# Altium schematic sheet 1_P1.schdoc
size 307 x 218 mm; Symbol: Drawing-Symbol_A4; Device: Drawing-Symbol_A4; Company: 嘉立创EDA; Version: V1.0; Page Size: A4; @Project Name: 光强检测_1; @Page Count: 1; @Update Date: 2025-09-07; @Create Date: 2025-08-30; @Schematic Name: Schematic1; @Page No: 1; @Page Name: P1; @Create Time: 12:52:20; @Update Time: 21:10:00; Width: 1170; Height: 825; Region Start: 1; X Region Count: 6; Y Region Count: 4; Blade Width: 10; Title Block Position: 3; @Board Name: Board1
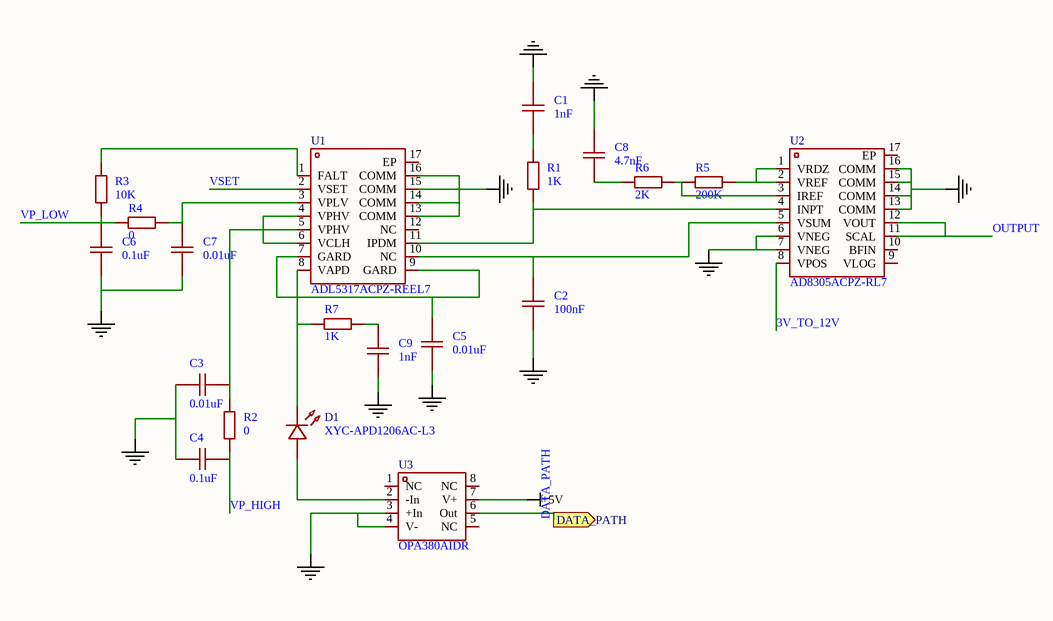
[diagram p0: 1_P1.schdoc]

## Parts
C1  1nF  [C0603]
C2  100nF  [C0603]
C3  0.01uF  [C0603]
C4  0.1uF  [C0603]
C5  0.01uF  [C0603]
C6  0.1uF  [C0603]
C7  0.01uF  [C0603]
C8  4.7nF  [C0603]
C9  1nF  [C0603]
D1  XYC-APD1206AC-L3  [LED1206-RD]
R1  1K  [R0603]
R2  0  [R0603]
R3  10K  [R0603]
R4  0  [R0603]
R5  200K  [R0603]
R6  2K  [R0603]
R7  1K  [R0603]
U1  ADL5317ACPZ-REEL7  [LFCSP-16_L3.0-W3.0-P0.50-BL-EP1.3-1]
U2  AD8305ACPZ-RL7  [LFCSP-16_L3.0-W3.0-P0.50-BL-EP1.3-1]
U3  OPA380AIDR  [SOIC-8_L5.0-W4.0-P1.27-LS6.0-BL]

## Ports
DATA_PATH (out)

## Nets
+5V: U3.7(V+)
GND: C1.2 C2.2 C3.1 C4.1 C5.1 C6.1 C7.1 C8.2 C9.1 U1.13(COMM) U1.14(COMM) U1.15(COMM) U1.16(COMM) U2.6(VNEG) U2.7(VNEG) U2.13(COMM) U2.14(COMM) U2.15(COMM) U2.16(COMM) U3.3(+In) U3.4(V-)
3V_TO_12V: U2.8(VPOS)
DATA_PATH: U3.6(Out) ; port DATA_PATH
OUTPUT: U2.11(SCAL) U2.12(VOUT)
VP_HIGH: C4.2 R2.2
VP_LOW: C6.2 R3.1 R4.1
VSET: U1.2(VSET)
NetC1_1: C1.1 R1.2
NetC2_1: C2.1 U1.10(NC) U2.5(VSUM)
NetC3_2: C3.2 R2.1 U1.4(VPHV) U1.5(VPHV) U1.6(VCLH)
NetC5_2: C5.2 U1.7(GARD) U1.9(GARD)
NetC7_2: C7.2 R4.2 U1.3(VPLV)
NetC8_1: C8.1 R6.1
NetC9_2: C9.2 R7.2
NetD1_1: D1.1(-) R7.1 U1.8(VAPD)
NetD1_2: D1.2(+) U3.2(-In)
NetR1_1: R1.1 U1.11(IPDM) U2.4(INPT)
NetR3_2: R3.2 U1.1(FALT)
NetR5_1: R5.1 R6.2 U2.3(IREF)
NetR5_2: R5.2 U2.1(VRDZ) U2.2(VREF)

Not connected (* = marked no-connect by the designer): U1 12(NC) 17(EP); U2 9(VLOG) 10(BFIN) 17(EP); U3 1(NC) 5(NC) 8(NC)

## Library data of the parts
C1-C9 = CAP_0603: Symbol: Capacitance; Convert to PCB: yes
D1 = XYC-APD1206AC-L3: Manufacturer: NEWOPTO(鑫永诚光电); Add into BOM: yes
R1-R7 = Res_0603: Symbol: 电阻; Convert to PCB: yes
U1 = ADL5317ACPZ-REEL7: Manufacturer: ADI(亚德诺); Add into BOM: yes; Voltage - Supply: 10V~80V
U2 = AD8305ACPZ-RL7: Manufacturer: ADI(亚德诺); Add into BOM: yes; Amplifier Type: 对数转换器
U3 = OPA380AIDR: Manufacturer: TI(德州仪器); Add into BOM: yes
